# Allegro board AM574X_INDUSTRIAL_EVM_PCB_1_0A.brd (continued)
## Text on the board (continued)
User.41: FIGURE | SIZE | 5.0 | 8.0 | DRILL CHART: L11_GND4 to BOTTOM | ALL UNITS ARE IN MILS | TOLERANCE | +0.0/-5.0 | +0.0/-8.0 | PLATED | QTY | 377 | 422
User.42: FIGURE | SIZE | 8.0 | DRILL CHART: L3_SIG1 to L10_SIG4 | ALL UNITS ARE IN MILS | TOLERANCE | +0.0/-8.0 | PLATED | QTY | 917
User.43: FIGURE | SIZE | 5.0 | 8.0 | DRILL CHART: L10_SIG4 to L11_GND4 | ALL UNITS ARE IN MILS | TOLERANCE | +0.0/-5.0 | +0.0/-8.0 | PLATED | QTY | 378 | 422
